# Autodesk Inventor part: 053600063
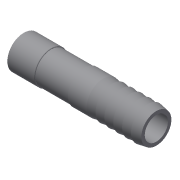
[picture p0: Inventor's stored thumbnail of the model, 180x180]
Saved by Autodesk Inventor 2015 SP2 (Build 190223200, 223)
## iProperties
Created: 2017-10
Part Number: 053600063
Material: Generic
Description: PLASSON HOSE NOZZLE-CEM. PVC 63
Document SubType Name: Modeling
Designer: KIM
Density: 1 g/cm^3
Appearance: Default
Author: KIM
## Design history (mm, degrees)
derived "053600.ipt"
feature "Solid1::053600.ipt"
tag "TaggingFeature1"
body "Solid1"
other parameters: "d0" = 118, "d1" = 170 deg, "d4" = 38, "d5" = 63, "d6" = 44.1, "d8" = 47.2, "d9" = 57.6, "d10" = 29.5, "d11" = 0.63, "d14" = 0.63, "d_" = 63, "H_" = 118, "L_" = 38
